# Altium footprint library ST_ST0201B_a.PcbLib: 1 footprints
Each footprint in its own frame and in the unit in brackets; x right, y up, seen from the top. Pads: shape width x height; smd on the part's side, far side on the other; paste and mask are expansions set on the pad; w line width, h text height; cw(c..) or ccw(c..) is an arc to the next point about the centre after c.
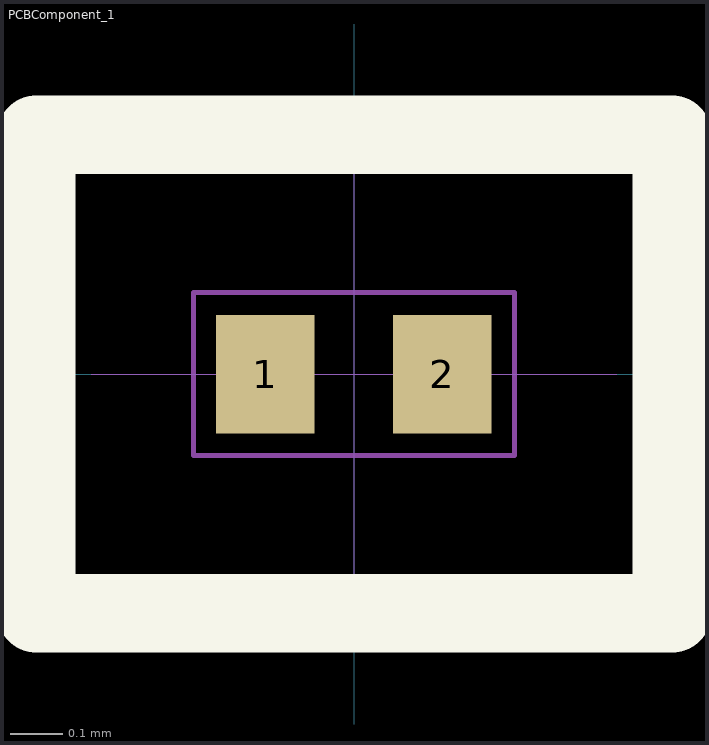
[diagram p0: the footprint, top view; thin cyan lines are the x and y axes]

## PCBComponent_1 [mm]
pads (2):
  rect 0.187x0.225 smd paste-20 mask+0.025: 1(-0.168,-0.001) 2(0.168,-0.001)
Top Overlay:
  lines w0.15: -0.605,-0.455 0.605,-0.455 0.605,0.455 -0.605,0.455 -0.605,-0.455
Top Paste:
  rectangle: 0.083,-0.105 0.253,0.105
  rectangle: -0.253,-0.105 -0.083,0.105
Mechanical 15:
  lines w0.001: -0.5,0 0.5,0 ; 0,-0.5 0,0.5
  lines w0.01: -0.305,-0.155 0.305,-0.155 0.305,0.155 -0.305,0.155 -0.305,-0.155
3D body: height 0.27, standoff 0, extent -0.305,-0.155 0.305,0.155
